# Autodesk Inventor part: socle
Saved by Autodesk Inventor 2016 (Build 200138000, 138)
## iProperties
Created: 2013-10
Part Number: socle
Material: Générique
Document SubType Name: Modeling
Designer: Bruno
Density: 1 g/cm^3
Appearance: Par défaut
Author: Bruno
Sending System: SolidWorks 2013
Last Author: christophe
Last Saved: 2014-02-15
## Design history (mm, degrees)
feature "Symétrie5"
node "Solide1"
